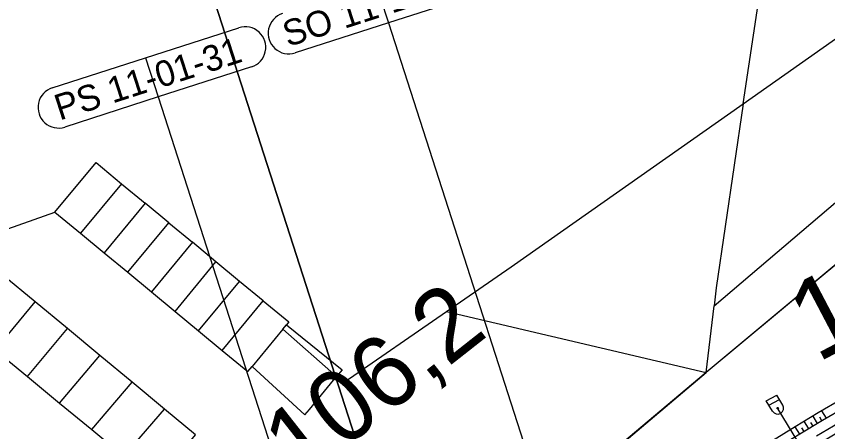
# Model space of a CAD drawing. Extents: x -758836 to -757729, y -1175316 to -1174366.
# Drawn here: x -758434.1 to -758355.4, y -1174805.6 to -1174765.3 of the extents above; entities that cross this region are included whole.
import ezdxf

# ---------------------------------------------------------------- set-up
doc = ezdxf.new("R2010")
doc.units = 0
for name, color, linetype in [('_NOR-návrh tenká', 7, 'Continuous'), ('_NOR-osa', 7, 'Continuous'), ('_NOR-pomocná', 7, 'Continuous'), ('_NOR-popis', 7, 'Continuous'), ('_NOR-svahy', 7, 'Continuous'), ('G_Obvod stavby', 7, 'Continuous'), ('Hranice parcel', 7, 'Continuous'), ('Vrstva 63', 7, 'Continuous'), ('Vrstva 7', 7, 'Continuous')]:
    doc.layers.add(name, color=color, linetype=linetype)

msp = doc.modelspace()

# ---------------------------------------------------------------- linework, layer by layer
at = {"layer": '_NOR-návrh tenká'}
for p, q in [((-758361.359, -1174802.548), (-758360.342, -1174802.008)), ((-758359.758, -1174802.968), (-758360.342, -1174802.008)), ((-758360.74, -1174803.566), (-758361.359, -1174802.548)), ((-758361.099, -1174802.976), (-758360.082, -1174802.436)), ((-758356.223, -1174809.884), (-758360.288, -1174803.203))]:
    msp.add_line(p, q, dxfattribs=at)
msp.add_circle((-758360.249, -1174803.267), 0.075, dxfattribs=at)
for centre, radius, start, end in [((-758205.34, -1175057.864), 295.6, 97.09776, 129.28488), ((-758205.34, -1175057.864), 294.75, 97.0979, 129.28474), ((-758205.34, -1175057.864), 293.75, 97.09807, 120.96729), ((-758205.34, -1175057.864), 292.25, 97.09832, 120.96729), ((-758205.34, -1175057.864), 291.3, 97.09848, 129.28417), ((-758205.34, -1175057.864), 290.55, 97.09861, 129.28404), ((-758360.249, -1174803.267), 0.575, 211.31834, 31.31834)]:
    msp.add_arc(centre, radius, start, end, dxfattribs=at)
at = {"layer": '_NOR-osa'}
msp.add_arc((-758205.34, -1175057.864), 293, 97.09819, 129.28445, dxfattribs=at)
at = {"layer": '_NOR-pomocná'}
for p, q in [((-758399.224, -1174762.097), (-758397.997, -1174765.904)), ((-758421.535, -1174769.284), (-758420.309, -1174773.091))]:
    msp.add_line(p, q, dxfattribs=at)
for points in [[(-758417.595, -1174755.224), (-758317.652, -1174723.031), (-758272.123, -1174864.38), (-758372.066, -1174896.572)], [(-758517.538, -1174787.416), (-758417.595, -1174755.224), (-758372.066, -1174896.572), (-758472.009, -1174928.764)]]:
    msp.add_lwpolyline(points, close=True, dxfattribs=at)
at = {"layer": '_NOR-popis'}
for points in [[(-758388.955, -1174762.992), (-758397.997, -1174765.904), (-758378.816, -1174825.453)], [(-758430.578, -1174772.196), (-758412.493, -1174766.371)], [(-758397.997, -1174765.904), (-758407.04, -1174768.817)], [(-758411.267, -1174770.178), (-758420.309, -1174773.091), (-758401.541, -1174831.358)], [(-758420.309, -1174773.091), (-758429.352, -1174776.004)]]:
    msp.add_lwpolyline(points, dxfattribs=at)
for centre, start, end in [((-758407.653, -1174766.913), 107.85402, 287.85473), ((-758411.88, -1174768.275), 287.85331, 107.85402), ((-758429.965, -1174774.1), 107.85402, 287.85473)]:
    msp.add_arc(centre, 2, start, end, dxfattribs=at)
at = {"layer": '_NOR-svahy'}
for points in [[(-758355.524, -1174804.245), (-758355.957, -1174803.514)], [(-758356.383, -1174804.756), (-758356.819, -1174804.027)], [(-758355.954, -1174804.501), (-758356.171, -1174804.135)], [(-758358.097, -1174805.787), (-758358.538, -1174805.06)], [(-758357.669, -1174805.528), (-758357.889, -1174805.165)], [(-758357.241, -1174805.27), (-758357.679, -1174804.542)], [(-758356.812, -1174805.013), (-758357.031, -1174804.648)]]:
    msp.add_lwpolyline(points, dxfattribs=at)
at = {"layer": 'G_Obvod stavby'}
msp.add_lwpolyline([(-758392.72, -1174840.756), (-758391.23, -1174838.56), (-758368.37, -1174821.64), (-758340.31, -1174807.33), (-758320.27, -1174796.89), (-758301, -1174790.21), (-758267.96, -1174782.93), (-758224.96, -1174775.27), (-758184.87, -1174772.83), (-758142.71, -1174770.26), (-758089.84, -1174768.68), (-758106.02, -1174731.44), (-758149.09, -1174725.67), (-758199.62, -1174726.6), (-758225.76, -1174732.36), (-758252.17, -1174738.18), (-758254.97, -1174739.34), (-758266.58, -1174744.16), (-758279.45, -1174749.49), (-758302.42, -1174759.02), (-758331.68, -1174770.24), (-758367.17, -1174799.81), (-758405.64, -1174832.2)], dxfattribs=at)
at = {"layer": 'Hranice parcel'}
for p, q in [((-758363.58, -1174773.76), (-758361.69, -1174760.96)), ((-758331.68, -1174770.24), (-758367.17, -1174799.81)), ((-758366.42, -1174793.34), (-758349.61, -1174779.02)), ((-758423.86, -1174781.5), (-758427.84, -1174786.31)), ((-758423.86, -1174781.5), (-758421.57, -1174783.39)), ((-758421.57, -1174783.39), (-758425.55, -1174788.2)), ((-758419.28, -1174785.29), (-758421.57, -1174783.39)), ((-758441.25, -1174788.13), (-758430.32, -1174784.25)), ((-758430.32, -1174784.25), (-758427.84, -1174786.31)), ((-758423.26, -1174790.09), (-758419.28, -1174785.29)), ((-758419.28, -1174785.29), (-758417, -1174787.18)), ((-758427.84, -1174786.31), (-758425.55, -1174788.2)), ((-758417, -1174787.18), (-758420.97, -1174791.99)), ((-758414.71, -1174789.07), (-758417, -1174787.18)), ((-758425.55, -1174788.2), (-758423.26, -1174790.09)), ((-758418.68, -1174793.88), (-758414.71, -1174789.07)), ((-758412.42, -1174790.97), (-758414.71, -1174789.07)), ((-758423.26, -1174790.09), (-758420.97, -1174791.99)), ((-758416.39, -1174795.77), (-758412.42, -1174790.97)), ((-758410.13, -1174792.86), (-758412.42, -1174790.97)), ((-758420.97, -1174791.99), (-758418.68, -1174793.88)), ((-758436.12, -1174797.63), (-758432.25, -1174792.96)), ((-758429.12, -1174795.55), (-758432.25, -1174792.96)), ((-758414.1, -1174797.67), (-758410.13, -1174792.86)), ((-758367.17, -1174799.81), (-758366.42, -1174793.34)), ((-758418.68, -1174793.88), (-758416.39, -1174795.77)), ((-758392.35, -1174793.89), (-758367.17, -1174799.81)), ((-758433, -1174800.2), (-758429.12, -1174795.55)), ((-758425.97, -1174798.15), (-758429.12, -1174795.55)), ((-758416.39, -1174795.77), (-758414.1, -1174797.67)), ((-758408.22, -1174795.6), (-758411.21, -1174799.23)), ((-758408.22, -1174795.6), (-758407.88, -1174795.19)), ((-758403.02, -1174800.2), (-758408.22, -1174795.6)), ((-758436.12, -1174797.63), (-758433, -1174800.2)), ((-758429.88, -1174802.77), (-758425.97, -1174798.15)), ((-758422.83, -1174800.74), (-758425.97, -1174798.15)), ((-758433, -1174800.2), (-758429.88, -1174802.77)), ((-758405.64, -1174832.2), (-758367.17, -1174799.81)), ((-758426.75, -1174805.34), (-758422.83, -1174800.74)), ((-758419.69, -1174803.35), (-758422.83, -1174800.74)), ((-758429.88, -1174802.77), (-758426.75, -1174805.34)), ((-758423.63, -1174807.91), (-758419.69, -1174803.35)), ((-758426.75, -1174805.34), (-758423.63, -1174807.91))]:
    msp.add_line(p, q, dxfattribs=at)
for points in [[(-758363.58, -1174773.76), (-758351.79, -1174765.46), (-758353.2, -1174761.75)], [(-758392.35, -1174793.89), (-758386.09, -1174789.57), (-758363.58, -1174773.76)], [(-758363.58, -1174773.76), (-758366.22, -1174791.6), (-758366.42, -1174793.34)], [(-758430.32, -1174784.25), (-758426.34, -1174779.45), (-758423.86, -1174781.5)], [(-758432.25, -1174792.96), (-758435.38, -1174790.37), (-758436.66, -1174791.92)], [(-758410.13, -1174792.86), (-758407.65, -1174794.91), (-758407.88, -1174795.19)], [(-758403.02, -1174800.2), (-758402.29, -1174800.74), (-758392.35, -1174793.89)], [(-758407.88, -1174795.19), (-758402.49, -1174799.56), (-758403.02, -1174800.2)], [(-758414.1, -1174797.67), (-758411.62, -1174799.72), (-758411.21, -1174799.23)], [(-758411.21, -1174799.23), (-758406.09, -1174803.91), (-758405.65, -1174803.38), (-758403.02, -1174800.2)], [(-758423.63, -1174807.91), (-758420.54, -1174810.5), (-758416.69, -1174805.84), (-758419.69, -1174803.35)]]:
    msp.add_lwpolyline(points, dxfattribs=at)

# ---------------------------------------------------------------- texts
at = {"layer": '_NOR-popis'}
for s, p in [('SO 11-11-01', (-758407.742, -1174768.255)), ('PS 11-01-31', (-758429.87, -1174775.383))]:
    msp.add_text(s, height=2.5, rotation=17.85402, dxfattribs=at).set_placement(p)
at = {"layer": 'Vrstva 63'}
msp.add_text('1015', height=7.7553, rotation=27.72064, dxfattribs=at).set_placement((-758356.425, -1174798.908))
at = {"layer": 'Vrstva 7'}
msp.add_text('106,2', height=6.9716, rotation=38.19355, dxfattribs=at).set_placement((-758406.498, -1174810.546))

doc.saveas('drawing.dxf')
